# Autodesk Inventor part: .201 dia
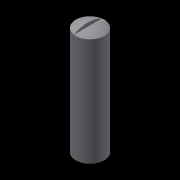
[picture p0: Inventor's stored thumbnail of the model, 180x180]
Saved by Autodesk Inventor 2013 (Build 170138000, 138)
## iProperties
Created: 2013-01
Part Number: .201 dia
Material: Generic
Document SubType Name: Modeling
Designer: John
Density: 1 g/cm^3
Author: John
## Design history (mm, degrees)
sketch "Sketch1"
  geometry: L1 (2.553, -0.688)-(2.553, 20.043); L2 (5.105, 0)-(5.105, 19.355); A1 r 5.08 centre (2.553, 14.963) between (5.105, 19.355) and (2.553, 20.043); A2 r 5.08 centre (2.553, 4.392) between (2.553, -0.688) and (5.105, 0); 1 further point
  constraints: 4 end point, 4 point on circle, 2 centre point, 1 parallel
revolve "Revolution1" sketch "Sketch1" stored, may be unused: angle "d6" = 90 deg
sketch "Sketch2"
  geometry: L1 (0, 0)-(5.105, 0) reference; L2 (0, 19.355)-(5.105, 19.355) reference; L3 (0, 19.355)-(0, 0) reference; L4 (5.105, 19.355)-(5.105, 0) reference; L5 (2.553, 19.355)-(2.912, 19.355); L6 (2.912, 19.355)-(2.912, 20.03); L7 (2.193, 19.355)-(2.193, 20.03); L8 (2.193, 19.355)-(2.912, 19.355); L9 (2.193, 0)-(2.193, -0.675); L10 (2.193, 0)-(2.912, 0); L11 (2.912, 0)-(2.912, -0.675); A1 r 5.08 centre (2.553, 14.963) between (5.105, 19.355) and (0, 19.355) reference; 4 further points
  constraints: 14 end point, 2 perpendicular, 2 point on circle, 1 midpoint, 1 point on line, 3 other
extrude "Extrusion1" cut sketch "Sketch2" stored distance "d7" = 25.4; taper "d8" = 0 deg
body "Solid1"
node "Projected Loop1"
